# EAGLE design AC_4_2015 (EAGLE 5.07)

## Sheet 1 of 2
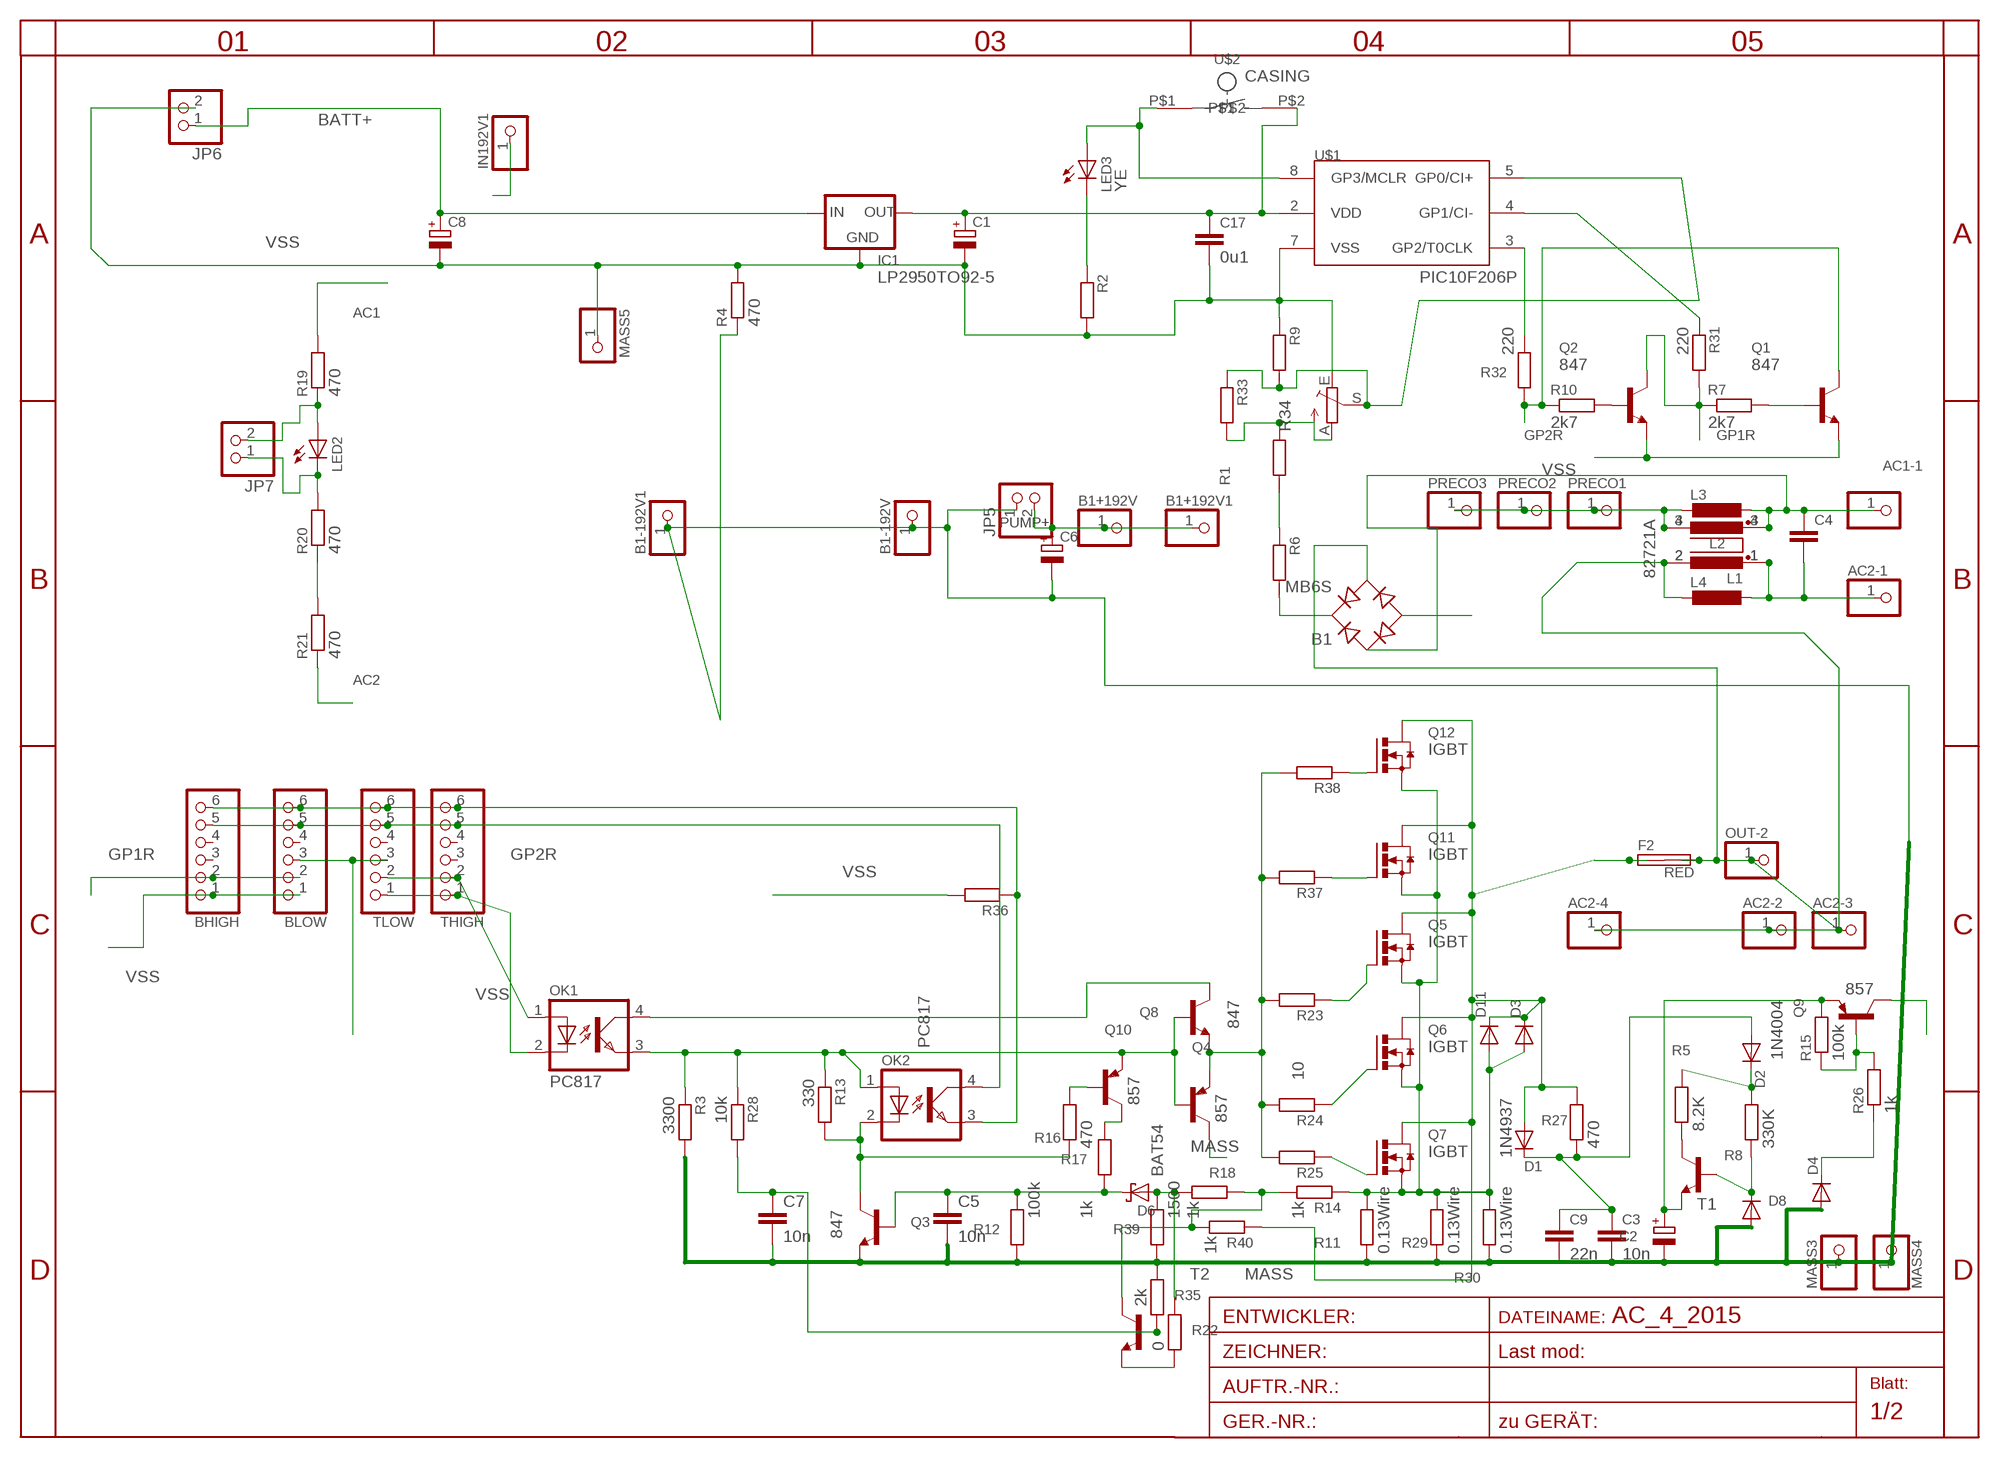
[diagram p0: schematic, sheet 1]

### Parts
AC1-1  PINHD-1X14.5MM  [1X4MM5]
AC2-1  PINHD-1X14.5MM  [1X4MM5]
AC2-2  PINHD-1X13MM2  [1X3MM2]
AC2-3  PINHD-1X13MM2  [1X3MM2]
AC2-4  PINHD-1X12MM3  [1X2MM3]
B1  MB6S  [SOIC-4]
B1+192V  PINHD-1X13MM2  [1X3MM2]
B1+192V1  PINHD-1X13MM2  [1X3MM2]
B1-192V  PINHD-1X13MM2  [1X3MM2]
B1-192V1  PINHD-1X13MM2  [1X3MM2]
BHIGH  PINHD-1X6  [1X06BOX]
BLOW  PINHD-1X6  [1X06BOX]
C1  CPOL-EUE5-6  [E5-6]
C2  CPOL-EUE2.5-5  [E2,5-5]
C3  10n  C-EU025_050-050X075  [C025_050-050X075]
C4  C-EU102_152-062X184  [C102_152-062X184]
C5  10n  C-EUC0805  [C0805]
C6  CPOL-EUE10-20  [EB20D]
C7  10n  C-EUC0805  [C0805]
C8  CPOL-EUE5-5  [E5-5]
C9  22n  C-EU102-043X133  [C102-043X133]
C17  0u1  C-EUC1206  [C1206]
D1  1N4937  1N4004DO41-10  [DO41-10]
D2  1N4004  [DO41-20]
D3  DIODE-SMC  [SMC]
D4  DIODE-MINIMELF  [MINIMELF]
D6  BAT54  [SOT23]
D8  DIODE-MINIMELF  [MINIMELF]
D11  DIODE-SMC  [SMC]
F2  SHK20L7MM5  [7MM5]
IC1  LP2950TO92-5  [T092-5]
IN192V1  PINHD-1X13MM2  [1X3MM2]
JP5  PINHD-1X2STR  [1X02]
JP6  PINHD-1X2STR  [1X02]
JP7  PINHD-1X2STR  [1X02]
L1  R1405VB1  [B1]
L2  82721A  [82721A]
L3  L-EU2200-15.24  [2200-15.24]
L4  L-EU2200-15.24  [2200-15.24]
LED2  LED3MM  [LED3MM]
LED3  YE  LEDCHIPLED_1206  [CHIPLED_1206]
MASS3  PINHD-1X13MM2  [1X3MM2]
MASS4  PINHD-1X13MM2  [1X3MM2]
MASS5  PINHD-1X11MM6  [1X1MM8]
OK1  PC817  [DIL04]
OK2  PC817  [DIL04]
OUT-2  PINHD-1X13MM2  [1X3MM2]
PRECO1  PINHD-1X12MM3  [1X2MM3]
PRECO2  PINHD-1X13MM2  [1X3MM2]
PRECO3  PINHD-1X13MM2  [1X3MM2]
Q1  847  BC847ALT1SMD  [SOT23]
Q2  847  BC847ALT1SMD  [SOT23]
Q3  847  BC846ALT1SMD  [SOT23]
Q4  857  BC857ALT1SMD  [SOT23-BEC]
Q5  IGBT  N-HEXFET_DPAK-  [TO252]
Q6  IGBT  N-HEXFET_DPAK-  [TO252]
Q7  IGBT  N-HEXFET_DPAK-  [TO252]
Q8  847  BC846ALT1SMD  [SOT23]
Q9  857  BC857ALT1SMD  [SOT23-BEC]
Q10  857  BC857ALT1SMD  [SOT23-BEC]
Q11  IGBT  N-HEXFET_DPAK-  [TO252]
Q12  IGBT  N-HEXFET_DPAK-  [TO252]
R1  R-EU_0207/30  [0207/30]
R2  R-EU_R0805  [R0805]
R3  3300  R-EU_R0805  [R0805]
R4  470  R-EU_0204/5  [0204/5]
R5  8.2K  R-EU_0204/5  [0204/5]
R6  R-EU_0207/60  [0207/60]
R7  2k7  R-EU_R0805  [R0805]
R8  330K  R-EU_0204/5  [0204/5]
R9  R-EU_R0805  [R0805]
R10  2k7  R-EU_R0805  [R0805]
R11  0.13Wire  R-EU_0204/5  [0204/5]
R12  100k  R-EU_R0805  [R0805]
R13  330  R-EU_R1206  [R1206]
R14  1k  R-EU_R0805  [R0805]
R15  100k  R-EU_R0805  [R0805]
R16  470  R-EU_R0805  [R0805]
R17  1k  R-EU_R1206  [R1206]
R18  1k  R-EU_R0805  [R0805]
R19  470  R-EU_0204/5  [0204/5]
R20  470  R-EU_0204/2V  [0204V]
R21  470  R-EU_0204/5  [0204/5]
R22  0  R-EU_R0805  [R0805]
R23  R-EU_0207/12  [0207/12]
R24  R-EU_0207/15  [0207/15]
R25  10  R-EU_0207/12  [0207/12]
R26  1k  R-EU_R0805  [R0805]
R27  470  R-EU_0207/10  [0207/10]
R28  10k  R-EU_R0805  [R0805]
R29  0.13Wire  R-EU_0204/5  [0204/5]
R30  0.13Wire  R-EU_0204/5  [0204/5]
R31  220  R-EU_R1206  [R1206]
R32  220  R-EU_R1206  [R1206]
R33  R-EU_R0805  [R0805]
R34  TRIM_EU-S64W  [S64W]
R35  2k  R-EU_R0805  [R0805]
R36  R-EU_0207/12  [0207/12]
R37  R-EU_0207/15  [0207/15]
R38  R-EU_0207/10  [0207/10]
R39  1500  R-EU_R0805  [R0805]
R40  1k  R-EU_R1206  [R1206]
T1  -NPN-TO92-EBC  [TO92-EBC]
T2  -NPN-TO92-EBC  [TO92-EBC]
THIGH  PINHD-1X6  [1X06BOX]
TLOW  PINHD-1X6  [1X06BOX]
U$1  PIC10F206P  [DIL8]
U$2  CASING  [CASING]

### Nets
AC1: AC1-1.1 B1.~1(AC1) C4.1 L1.3 L2.4 L3.1 R19.2
AC2: R21.1
ACN: AC2-1.1 C4.2 L1.1 L2.1 L4.1
BATT+: BLOW.3 C8.+ IC1.3(IN) JP6.1 TLOW.3
BLACK: L1.4 L2.3 L3.2 PRECO1.1 PRECO2.1 PRECO3.1 ; also sheet 2
D1: D1.A D3.C D11.C F2.1A F2.1B Q5.3(D) Q6.3(D) Q7.3(D) Q11.3(D) Q12.3(D) R27.2 R40.2
GP1R: BHIGH.2 BLOW.2 Q2.3(C) R7.1 R31.2
GP2R: OK1.1(A) Q1.3(C) R10.1 R32.2 THIGH.2 TLOW.2
GP3: BHIGH.6 BLOW.6 LED3.A OK2.3(EMIT) R36.1 THIGH.6 TLOW.6 U$1.8(GP3/MCLR) U$2.P$1
MASS: B1-192V1.1 B1-192V.1 B1.- C2.- C3.3 C5.2 C6.- C7.2 C9.2 D4.A D8.A JP5.1 MASS3.1 MASS4.1 Q3.2(E) Q4.C R3.2 R4.1 R11.1 R12.2 R29.1 R30.1 R35.2 R39.2 ; also sheet 2
N$1: R9.2 R33.1 R34.S U$1.5(GP0/CI+)
N$2: C3.1 C9.1 D1.C D2.A R27.1
N$3: R1.2 R6.1
N$4: Q2.1(B) R10.2
N$6: JP7.2 LED2.A R19.1
N$7: Q1.1(B) R7.2
N$9: JP7.1 LED2.K(C) R20.2
N$11: C5.1 D6.3(C) Q3.1(B) R12.1 R17.2
N$12: OK2.2(C) Q3.3(C) R13.2 R16.1
N$13: R20.1 R21.2
N$14: R14.1 R18.2 R40.1 T2.C
N$15: LED3.C R2.1
N$16: Q10.B R16.2
N$17: Q10.C R17.1
N$20: D2.C R5.2 R8.2
N$25: Q12.1(G) R38.1
N$26: Q6.1(G) R24.1
N$27: Q5.1(G) R23.1
N$33: B1.+ R6.2
N$34: R5.1 T1.C
N$35: D4.C R26.1
N$36: D8.C R8.1 T1.B
N$37: Q4.E Q8.2(E) R23.2 R24.2 R25.2 R37.2 R38.2
N$38: C2.+ Q9.E R15.2 T1.E
N$39: R31.1 U$1.4(GP1/CI-)
N$40: C7.1 R28.2 R35.1 T2.B
N$41: Q9.B R15.1 R26.2
N$42: R1.1 R33.2 R34.A
N$43: R32.1 U$1.3(GP2/T0CLK)
N$45: R22.1 T2.E
N$46: Q11.1(G) R37.1
N$47: Q7.1(G) R25.1
N$48: D6.1(A) R18.1 R22.2 R39.1
PP1: OK1.3(EMIT) OK2.1(A) Q4.B Q8.1(B) Q10.E R3.1 R13.1 R28.1
PUMP+: B1+192V1.1 B1+192V.1 C6.+ IN192V1.1 JP5.2 ; also sheet 2
RED: AC2-2.1 AC2-3.1 AC2-4.1 B1.~2(AC2) F2.2A F2.2B L1.2 L2.2 L4.2 OUT-2.1 ; also sheet 2
SRC1: D3.A D11.A Q5.2(S) Q6.2(S) Q7.2(S) Q11.2(S) Q12.2(S) R11.2 R14.2 R29.2 R30.2
V_OK: OK1.4(COL) Q8.3(C) Q9.C
VDD: BHIGH.5 BLOW.5 C1.+ C17.1 IC1.1(OUT) OK2.4(COL) THIGH.5 TLOW.5 U$1.2(VDD) U$2.P$2
VSS: BHIGH.1 BLOW.1 C1.- C8.- C17.2 IC1.2(GND) JP6.2 MASS5.1 OK1.2(C) Q1.2(E) Q2.2(E) R2.2 R4.2 R9.1 R34.E R36.2 THIGH.1 TLOW.1 U$1.7(VSS)
Unconnected: BHIGH.3 BHIGH.4 BLOW.4 THIGH.3 THIGH.4 TLOW.4

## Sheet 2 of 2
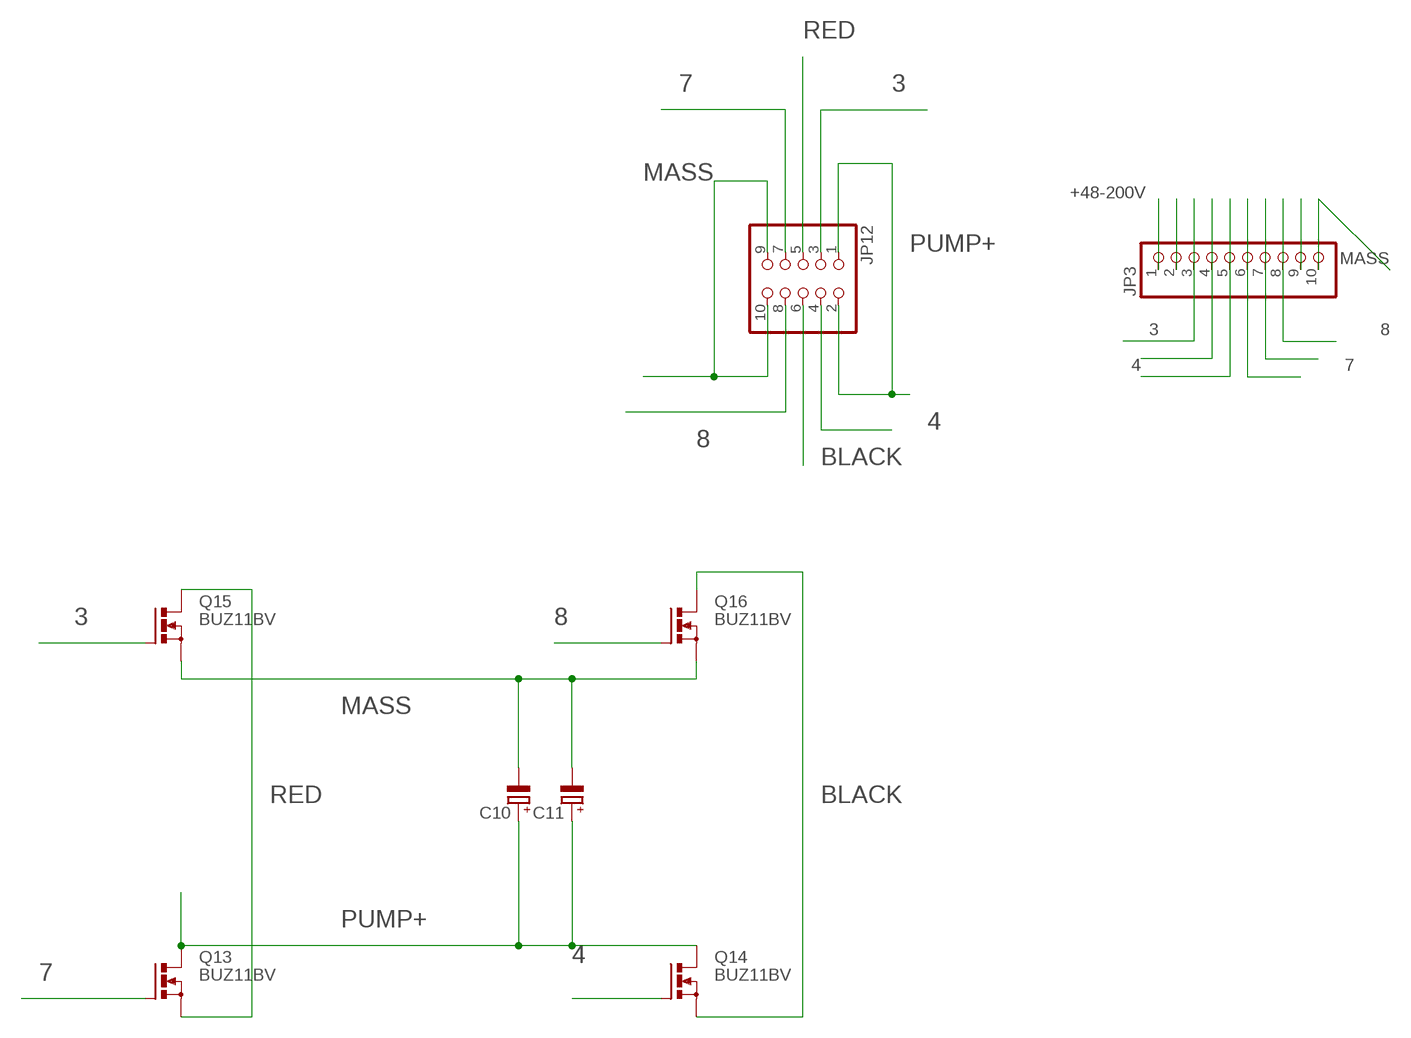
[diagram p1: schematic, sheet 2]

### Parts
C10  CPOL-EUE7.5-18  [E7,5-18]
C11  CPOL-EUE7.5-18  [E7,5-18]
JP3  PINHD-1X10  [1X10WIDE]
JP12  PINHD-2X5  [2X05]
Q13  BUZ11BV  [TO220BV]
Q14  BUZ11BV  [TO220BV]
Q15  BUZ11BV  [TO220BV]
Q16  BUZ11BV  [TO220BV]

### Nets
3: JP3.3 JP12.3 Q15.G
4: JP3.4 JP12.4 Q14.G
7: JP3.7 JP12.7 Q13.G
8: JP3.8 JP12.8 Q16.G
+48-200V: JP3.1
BLACK: JP3.6 JP12.6 Q14.S Q16.D ; also sheet 1
MASS: C10.- C11.- JP3.10 JP12.9 JP12.10 Q15.S Q16.S ; also sheet 1
N$44: JP3.2
N$49: JP3.9
PUMP+: C10.+ C11.+ JP12.1 JP12.2 Q13.D Q14.D ; also sheet 1
RED: JP3.5 JP12.5 Q13.S Q15.D ; also sheet 1

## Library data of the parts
AC1-1 AC2-1-AC2-4 B1+192V B1+192V1 B1-192V B1-192V1 IN192V1 MASS3-MASS5 OUT-2 PRECO1-PRECO3 = pinhead:PINHD-1X1: PIN HEADER
B1 = rectifier:MB*S: Bridge Rectifier Source: http://www.fairchildsemi.com/ds/MB/MB6S.pdf
BHIGH BLOW THIGH TLOW = pinhead:PINHD-1X6: PIN HEADER
C1 C2 C8 = rcl-2:CPOL-EU: POLARIZED CAPACITOR, European symbol
C3 C9 C17 = rcl-2:C-EU: CAPACITOR, European symbol
C4 C5 C7 = rcl:C-EU: CAPACITOR, European symbol
C6 C10 C11 = rcl:CPOL-EU: POLARIZED CAPACITOR, European symbol
D1 D2 = diode:1N4004: DIODE
D3 D4 D8 D11 = diode:DIODE-: DIODE
D6 = diode:BAT54: Schottky Diodes
F2 = fuse:SHK20L: FUSE HOLDER 5 x 20 mm, SH contact, SHH1 Schukat, E1073 Buerklin
IC1 = v-reg:LP2950?*: Source: http://cache.national.com/ds/LP/LP2950.pdf
JP3 = pinhead:PINHD-1X10: PIN HEADER
JP5-JP7 = pinhead:PINHD-1X2: PIN HEADER
JP12 = pinhead:PINHD-2X5: PIN HEADER
L1 = inductor-nkl:R1405V: Übertrager (verlustarm) bis typ. 400kHz Power transformer (low loss) up to typ. 400kHz
L2 = inductors:82721A: FILTER
L3 L4 = rcl:L-EU: INDUCTOR, European symbol
LED2 LED3 = led:LED: LED
OK1 OK2 = optocoupler:PC817: SHARP OPTO COUPLER
Q1 Q2 = transistor-npn:BC847*: NPN Transistor
Q3 Q8 = transistor-npn:BC846*: NPN Transistor
Q4 Q9 Q10 = transistor-pnp:BC857*: PNP Transistror
Q5-Q7 Q11 Q12 = transistor-power:N-HEXFET_?-*: HEXFET® Power MOSFET
Q13-Q16 = transistor-power:BUZ11: N-CHANNEL MOS FET
R1-R33 R35-R40 = rcl-2:R-EU_: RESISTOR, European symbol
R34 = pot:TRIM_EU-: POTENTIOMETER
T1 T2 = transistor-neu-to92:*-NPN-: NPN Transistror
U$1 = microchip-5:PIC10F2*: uPC nW 0,25/0,5k Program Flash memory Comparator
U$2 = button:CASING

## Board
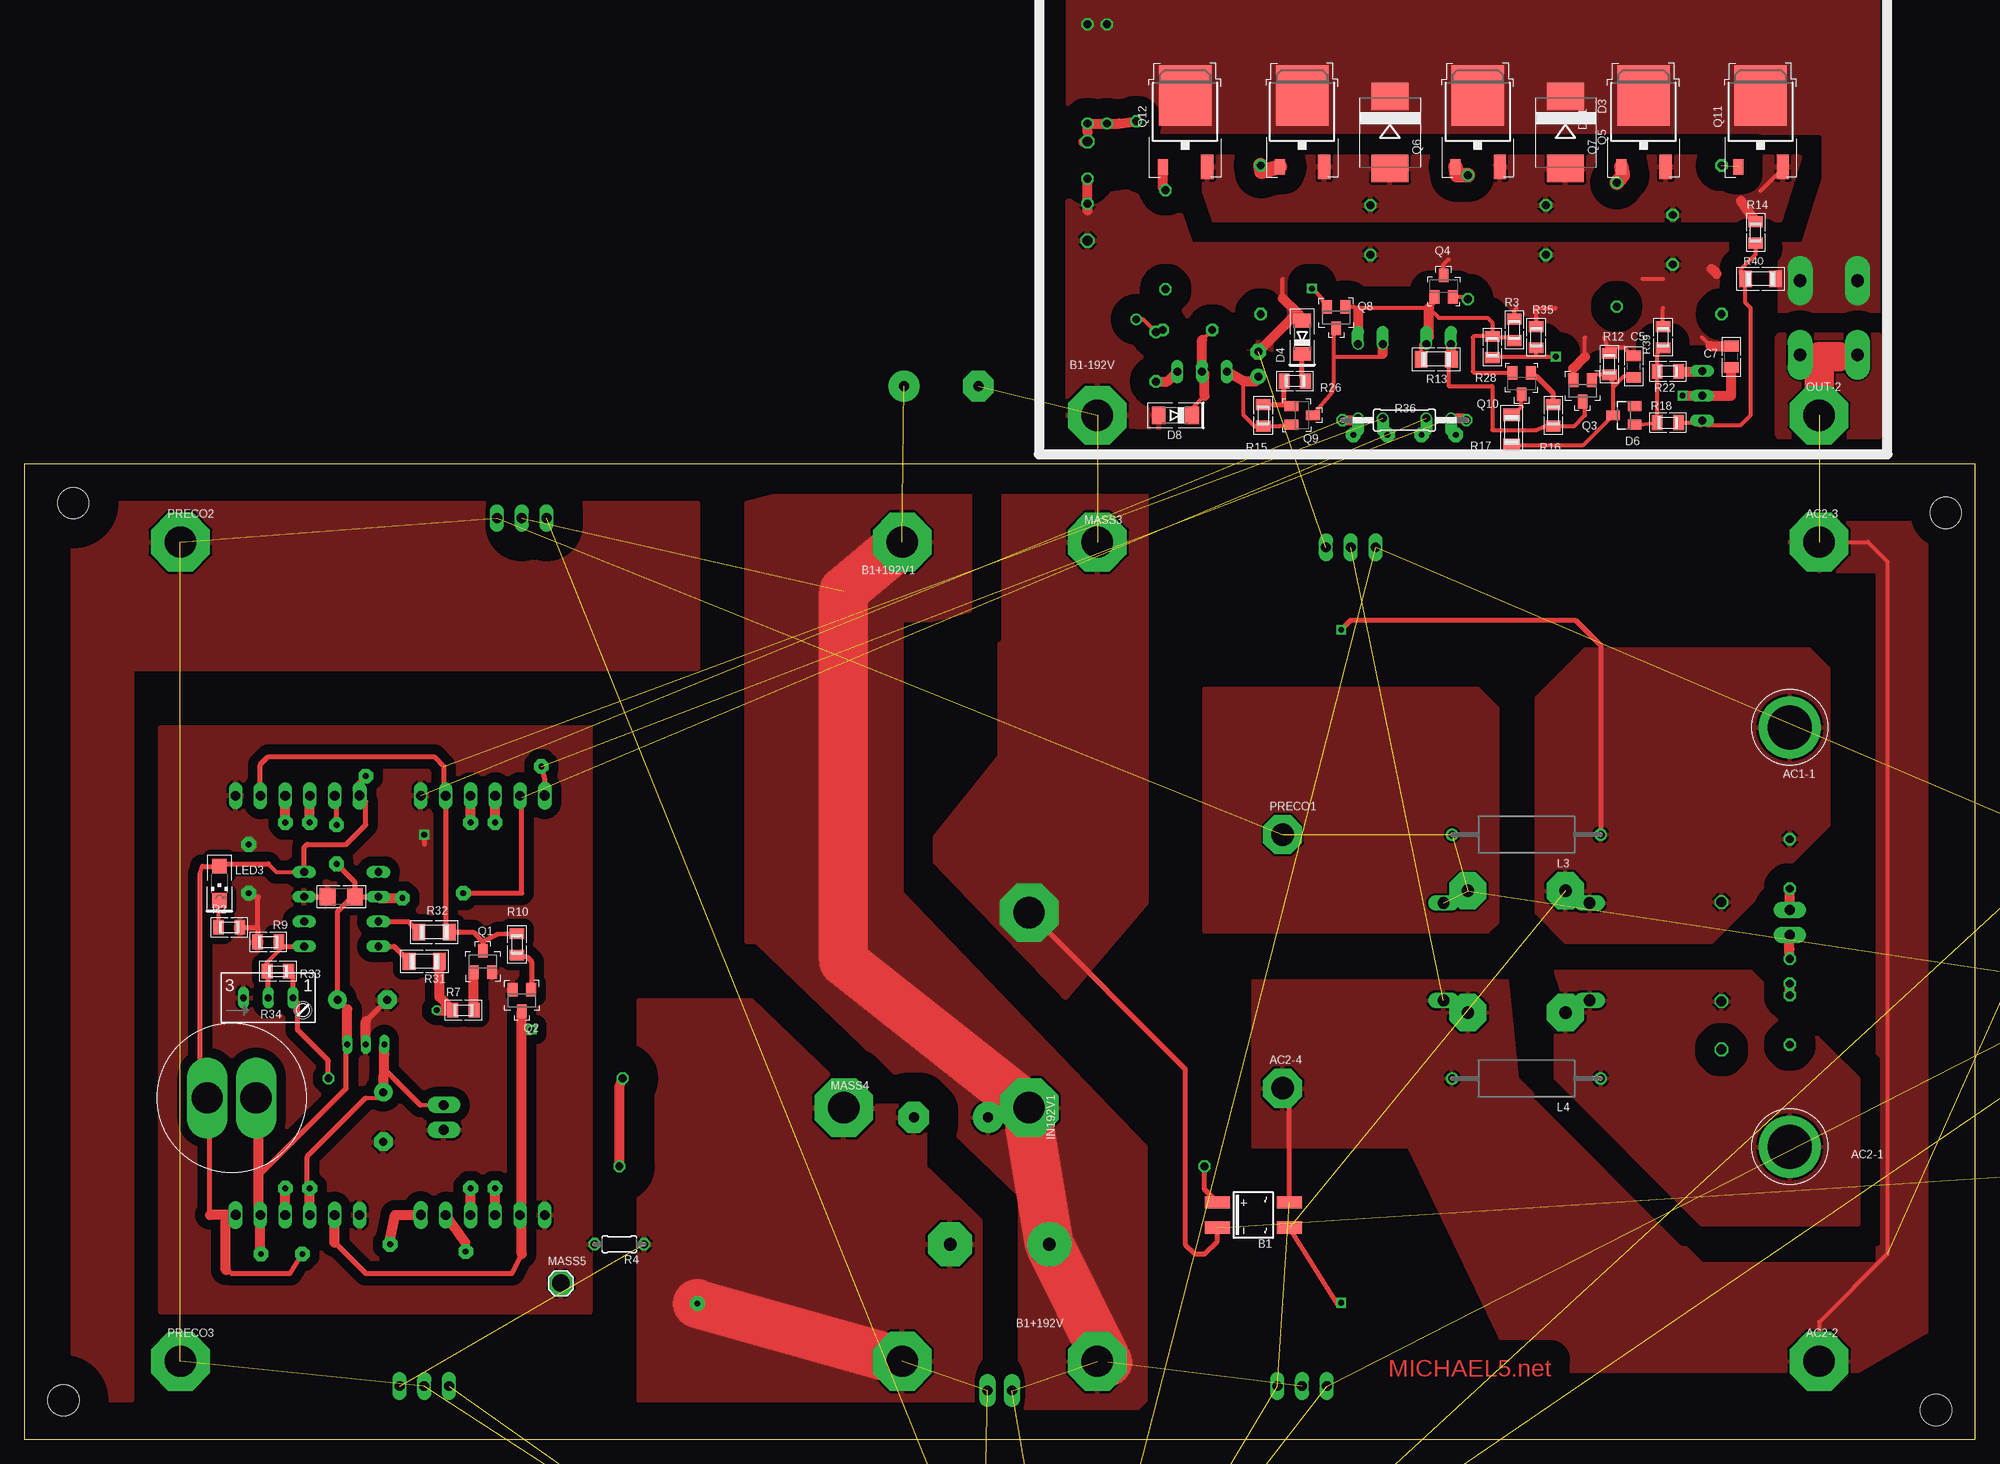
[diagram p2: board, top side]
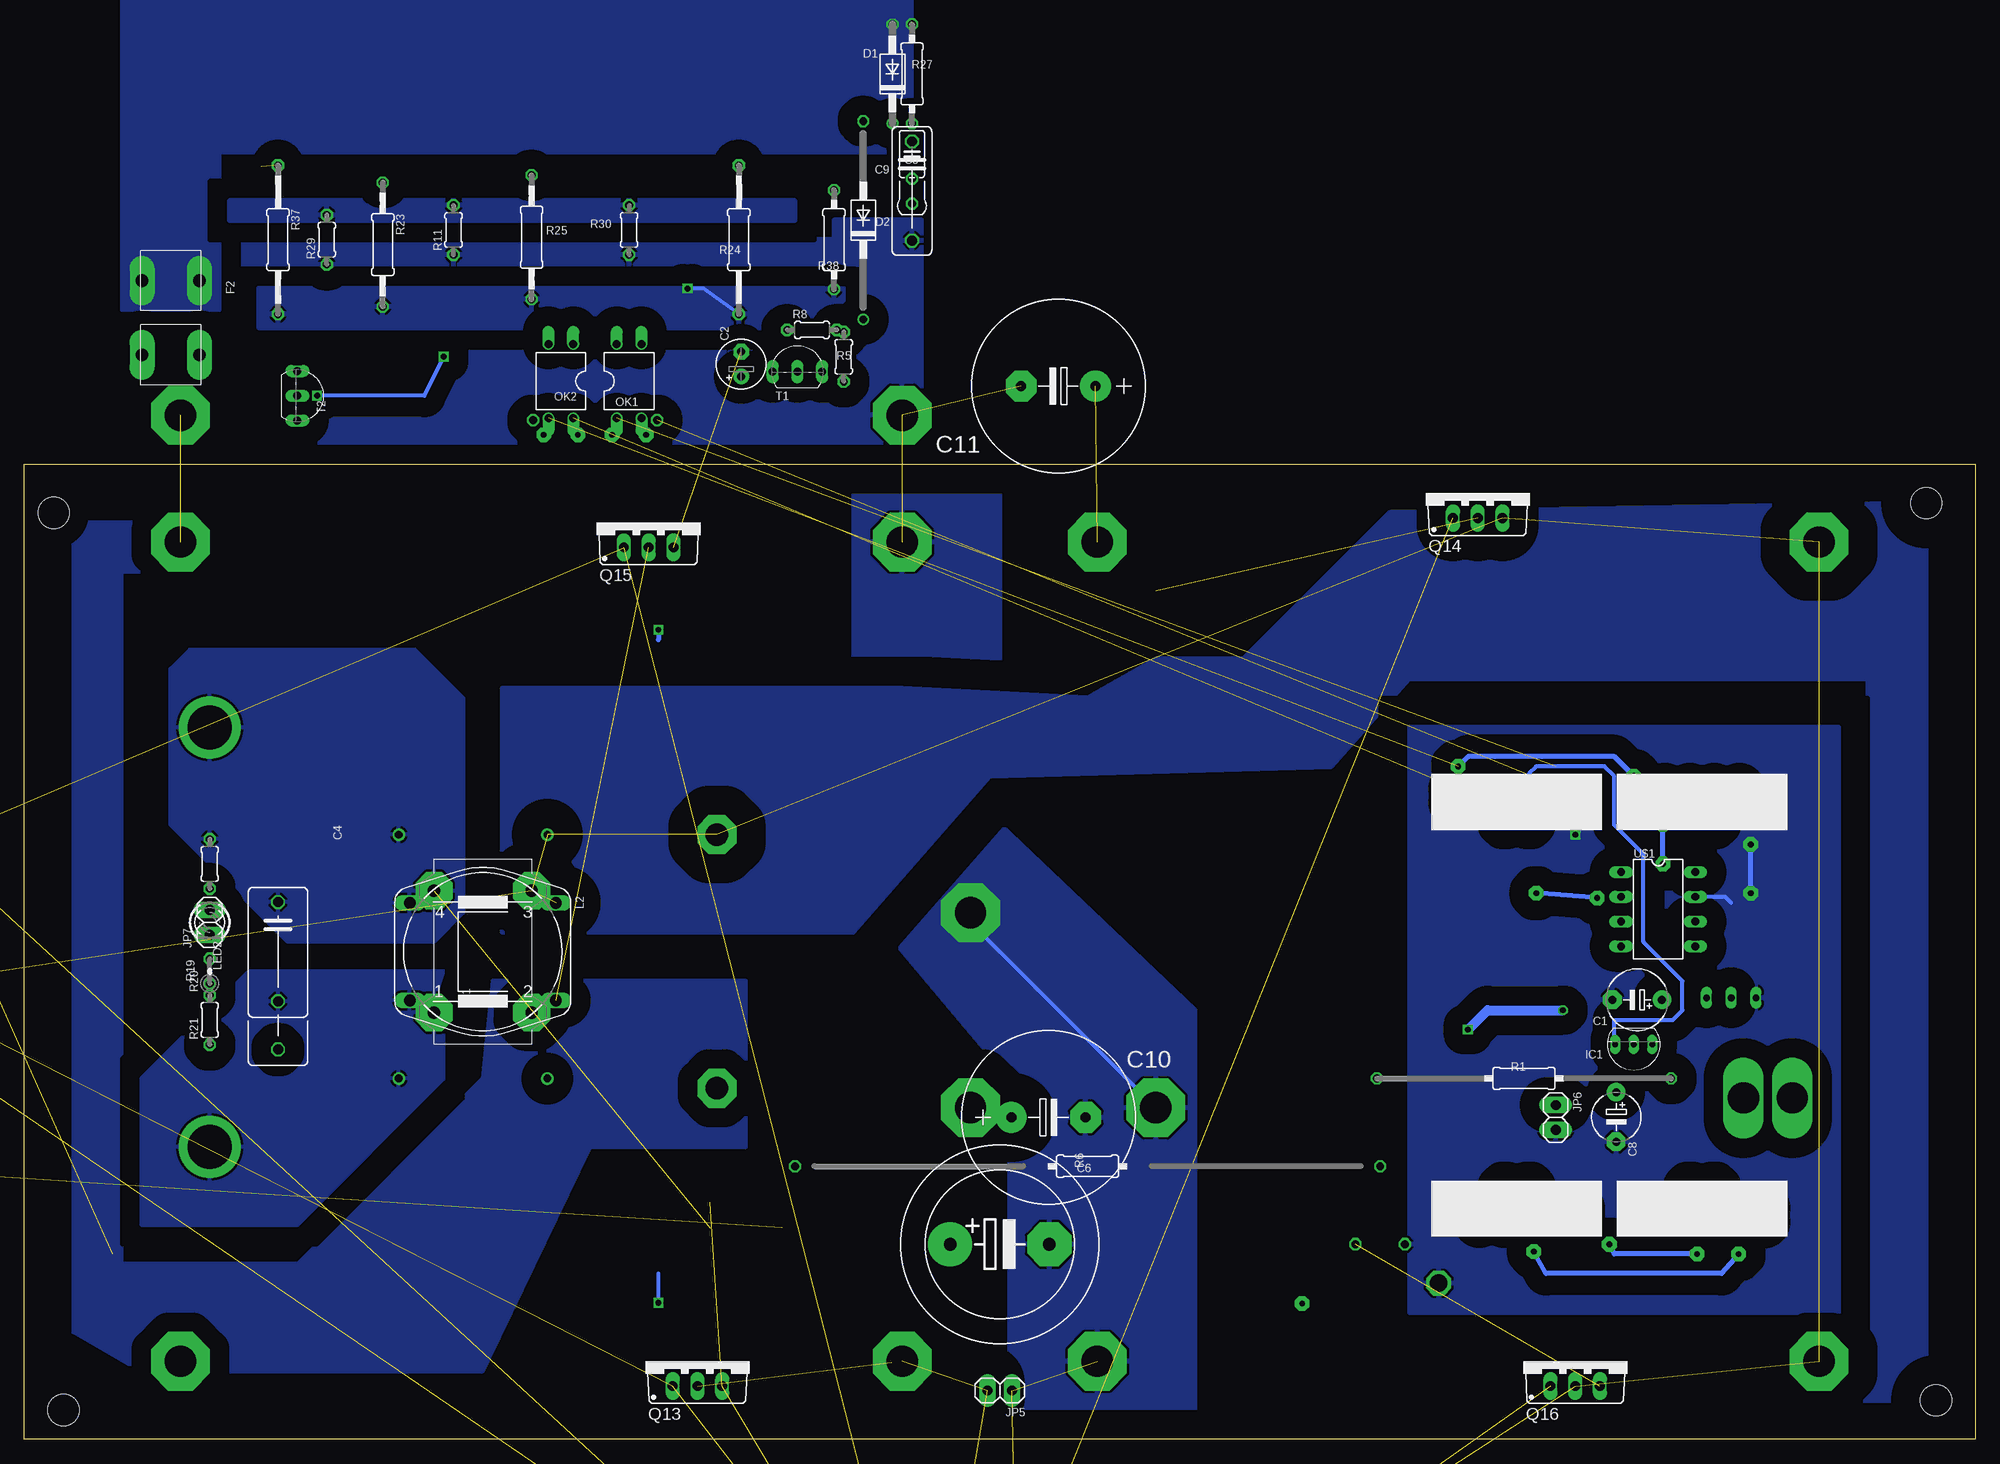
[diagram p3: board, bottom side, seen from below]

Size 200 x 100 mm. Coordinates in mm from the lower left corner, seen from the top.
Outline: 0,0 200,0 200,100 0,100 0,0
Copper layers (1*16): Top 0.035mm / dielectric 1.5mm / Bottom 0.035mm
Design rules "default *": minimum track width 12mil, minimum drill 24mil, track to track 8mil, track to pad 8mil, pad to pad 8mil, via to via 8mil, smd to smd 8mil, copper to edge 40mil, drill to drill 8mil, minimum pad ring 8mil, minimum via ring 8mil, stop-mask expansion 4mil, vias tented up to drill 0mil, thermal gap 10mil
Holes 3.2 mm at 5,96 4,4 197,95 196,3

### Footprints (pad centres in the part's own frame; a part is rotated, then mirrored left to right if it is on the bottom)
1X4MM5 = drill 4.5 pad 6.35 round: 1 0,0
1X3MM2 = drill 3.2 pad 6 octagon: 1 0,0
1X2MM3 = drill 2.3 pad 4 octagon: 1 0,0
SOIC-4 = smd 1.27 x 2.54: + 1.3,3.685; - -1.3,3.685; ~1 -1.3,-3.685; ~2 1.3,-3.685
1X06BOX = drill 1 long: 1 -6.35,0; 2 -3.81,0; 3 -1.27,0; 4 1.27,0; 5 3.81,0 | drill 1.016 long: 6 6.35,0
E5-6 = drill 0.813 pad 1.905 round: + -2.54,0 | drill 0.813 pad 1.905 octagon: - 2.54,0
E2,5-5 = drill 0.813 pad 1.6 round: + -1.27,0 | drill 0.813 pad 1.6 octagon: - 1.27,0
C025_050-050X075 = drill 0.813 octagon: 1 -3.81,0; 2 0,0; 3 2.54,0
C102_152-062X184 = drill 1.016 octagon: 1 -5.08,0; 2 5.08,0; 3 10.033,0
C0805 = smd 1.1 x 1.5: 1 -1.1,0; 2 1.1,0
EB20D = drill 1.3 pad 4.5 round: + -5.08,0 | drill 1.3 pad 4.5 octagon: - 5.08,0
E5-5 = drill 0.813 pad 1.905 round: + -2.54,0 | drill 0.813 pad 1.905 octagon: - 2.54,0
C102-043X133 = drill 1.016 octagon: 1 -5.08,0; 2 5.08,0
E7,5-18 = drill 1.016 pad 3.15 round: + -3.81,0 | drill 1.016 pad 3.15 octagon: - 3.81,0
C1206 = smd 1.6 x 1.8: 1 -1.4,0; 2 1.4,0
DO41-10 = drill 0.8 octagon: A 5.08,0 | drill 0.8 round: C -5.08,0
DO41-20 = drill 0.8 octagon: A 10.16,0 | drill 0.8 round: C -10.16,0
SMC = smd 2.8 x 3.8: A 3.7,0; C -3.7,0
MINIMELF = smd 1.4 x 1.8: A 1.7,0; C -1.7,0
SOT23 = smd 1 x 1.4: 1 -0.95,-1.1; 2 0.95,-1.1; 3 0,1.1
7MM5 = drill 1.3 pad 2.54 long: 1A -3.8,2.94; 1B -3.8,-2.94; 2A 3.8,2.94; 2B 3.8,-2.94
T092-5 = drill 0.6 pad 0.813 long: 1 -1.905,0; 2 0,0; 3 1.905,0
1X10WIDE = drill 1.016 long: 1 -22.86,0; 2 -17.78,0; 3 -12.7,0; 4 -7.62,0; 5 -2.54,0; 6 2.54,0; 7 7.62,0; 8 12.7,0; 9 17.78,0; 10 22.86,0
1X02 = drill 1.016 pad 1.676 long: 1 -1.27,0; 2 1.27,0
2X05 = drill 1.016 octagon: 1 -5.08,-1.27; 2 -5.08,1.27; 3 -2.54,-1.27; 4 -2.54,1.27; 5 0,-1.27; 6 0,1.27; 7 2.54,-1.27; 8 2.54,1.27; 9 5.08,-1.27; 10 5.08,1.27
B1 = drill 1.27 pad 3.81 octagon: 1 -6.25,5; 2 -6.25,-5; 3 6.25,5; 4 6.25,-5
82721A = drill 1.194 long: 1 7.493,5.004; 2 -7.493,5.004; 3 -7.493,-5.004; 4 7.493,-5.004
2200-15.24 = drill 0.8 pad 1.27 round: 1 -7.62,0; 2 7.62,0
LED3MM = drill 0.8 pad 1.27 octagon: A -1.27,0; K 1.27,0
CHIPLED_1206 = smd 1.5 x 1.5: A 0,-1.75; C 0,1.75
1X1MM8 = drill 1.8 pad 2.54 octagon: 1 0,0
DIL04 = drill 0.813 offset: 1 -1.27,-3.81; 2 1.27,-3.81; 3 1.27,3.81; 4 -1.27,3.81
SOT23-BEC = smd 1 x 1.4: B -0.95,-1.1; C 0,1.1; E 0.95,-1.1
TO252 = smd 1 x 1.6: 1 -2.28,-3.53 | smd 1.27 x 2.54: 2 2.28,-3.53 | smd 5.4 x 6.2: 3 0,3.77
TO220BV = drill 1.016 long: D 0,-2.54; G -2.54,-2.54; S 2.54,-2.54
0207/30 = drill 0.813 octagon: 1 -15.08,0; 2 15.08,0
R0805 = smd 1.1 x 1.5: 1 -1.1,0; 2 1.1,0
0204/5 = drill 0.8 pad 1.27 octagon: 1 -2.54,0; 2 2.54,0
0207/60 = drill 0.813 octagon: 1 -30,0; 2 30,0
R1206 = smd 1.3 x 1.7: 1 -1.55,0; 2 1.55,0
0204V = drill 0.8 pad 1.27 octagon: 1 -1.27,0; 2 1.27,0
0207/12 = drill 0.813 octagon: 1 -6.35,0; 2 6.35,0
0207/15 = drill 0.8 pad 1.27 octagon: 1 -7.62,0; 2 7.62,0
0207/10 = drill 0.813 octagon: 1 -5.08,0; 2 5.08,0
S64W = drill 0.7 long: A 2.54,1.27; E -2.54,1.27; S 0,1.27
TO92-EBC = drill 0.813 long: B 0,-1.27; C 2.54,-1.27; E -2.54,-1.27
DIL8 = drill 0.8 long: 1 -3.81,-3.81; 2 -1.27,-3.81; 3 1.27,-3.81; 4 3.81,-3.81; 5 3.81,3.81; 6 1.27,3.81; 7 -1.27,3.81; 8 -3.81,3.81
CASING = drill 3.2 pad 3.81 long: P$1 -2.5,0; P$2 2.5,0

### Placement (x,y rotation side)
AC1-1  181,73 180 top
AC2-1  181,30 180 top
AC2-2  184,8 0 top
AC2-3  184,92 0 top
AC2-4  129,36 0 top
B1  126,23 90 top
B1+192V  110,8 0 top
B1+192V1  90,92 180 top
B1-192V  not placed on the board
B1-192V1  90,8 0 top
BHIGH  47,23 0 bottom
BLOW  28,23 0 bottom
C1  34.65,45.07 180 bottom
C2  126.5,110.25 90 bottom  (outside the outline)
C3  109,129.25 270 bottom  (outside the outline)
C4  174,50 270 bottom
C5  165,110 90 top  (outside the outline)
C6  100,20 0 bottom
C7  175,111 90 top  (outside the outline)
C8  36.8,33.05 270 bottom
C9  109,128 270 bottom  (outside the outline)
C10  95,33 0 bottom
C11  not placed on the board
C17  32.49,55.63 180 top
D1  111,140 90 bottom  (outside the outline)
D2  114,125 90 bottom  (outside the outline)
D3  not placed on the board
D4  131,113 90 top  (outside the outline)
D6  164,105 90 top  (outside the outline)
D8  118,105 180 top  (outside the outline)
D11  not placed on the board
F2  185,115 270 bottom  (outside the outline)
IC1  35,40.5 180 bottom
IN192V1  103,34 270 top
JP3  not placed on the board
JP5  100,5 180 bottom
JP6  43,33 270 bottom
JP7  181,53 90 bottom
JP12  not placed on the board
L1  153,50 90 bottom
L2  153,50 180 bottom
L3  154,62 180 top
L4  154,37 180 top
LED2  181,53 270 bottom
LED3  20,57 180 top
MASS3  110,92 0 top
MASS4  84,34 0 top
MASS5  55,16 0 top
OK1  138,108.5 0 bottom  (outside the outline)
OK2  145,108.5 180 bottom  (outside the outline)
OUT-2  184,105 0 top  (outside the outline)
PRECO1  129,62 0 top
PRECO2  16,92 0 top
PRECO3  16,8 0 top
Q1  47,49 0 top
Q2  51,45 180 top
Q3  159.75,107.5 180 top  (outside the outline)
Q4  145.5,118.25 0 top  (outside the outline)
Q5  166,134 0 top  (outside the outline)
Q6  131,134 0 top  (outside the outline)
Q7  149,134 0 top  (outside the outline)
Q8  134.5,115 180 top  (outside the outline)
Q9  131,105 270 top  (outside the outline)
Q10  153.5,108.25 180 top  (outside the outline)
Q11  178,134 0 top  (outside the outline)
Q12  119,134 0 top  (outside the outline)
Q13  131,8 0 bottom
Q14  51,97 0 bottom
Q15  136,94 0 bottom
Q16  41,8 0 bottom
R1  46.25,37 180 bottom
R2  21,52.5 0 top
R3  152.75,113.75 90 top  (outside the outline)
R4  61,20 180 top
R5  116,111 90 bottom  (outside the outline)
R6  91,28 180 bottom
R7  45,44 0 top
R8  119.25,113.75 0 bottom  (outside the outline)
R9  25,51 0 top
R10  50.5,50.75 270 top
R11  not placed on the board
R12  162.5,110.25 90 top  (outside the outline)
R13  144.75,110.75 0 top  (outside the outline)
R14  177.5,123.75 90 top  (outside the outline)
R15  127,105 270 top  (outside the outline)
R16  156.75,105 90 top  (outside the outline)
R17  152.5,103.5 270 top
R18  168.5,104.25 0 top  (outside the outline)
R19  181,59 90 bottom
R20  181,48 90 bottom
R21  181,43 90 bottom
R22  168.5,109.5 180 top  (outside the outline)
R23  163.25,122.5 270 bottom  (outside the outline)
R24  126.75,123 270 bottom  (outside the outline)
R25  148,123.25 270 bottom  (outside the outline)
R26  130.25,108.5 180 top  (outside the outline)
R27  109,140 90 bottom  (outside the outline)
R28  150.5,112 270 top  (outside the outline)
R29  not placed on the board
R30  not placed on the board
R31  41,49 0 top
R32  42,52 0 top
R33  26,48 0 top
R34  25,44 0 top
R35  155,113 90 top  (outside the outline)
R36  141.5,104.5 180 top  (outside the outline)
R37  not placed on the board
R38  117,123 270 bottom  (outside the outline)
R39  168,113 90 top  (outside the outline)
R40  178,119 0 top  (outside the outline)
T1  120.75,110.75 0 bottom  (outside the outline)
T2  170.75,107 270 bottom  (outside the outline)
THIGH  28,66 180 bottom
TLOW  47,66 180 bottom
U$1  32.49,54.36 270 bottom
U$2  21.25,35 0 top

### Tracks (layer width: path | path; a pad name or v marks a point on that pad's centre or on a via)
3  (2 unrouted)
4  (2 unrouted)
7  (2 unrouted)
8  (2 unrouted)
AC1  (via drill 0.6)  (1 unrouted)
  Top 0.406: v135,14 134.7,13.7
  Top 0.5: 134.7,13.7 B1.~1 | L3.1 161.62,81.38 159,84 136,84 v135,83
  Bottom 0.406: v135,14 135,17
  Bottom 0.5: v135,83 135,82
  pour Bottom (isolate 2): 155,65 155,54 158,51 173,51 185,63 185,79 183,81 160,81 155,76
  pour Top (isolate 2): 155,65 155,54 158,51 173,51 185,63 185,79 183,81 160,81 155,76
ACN
  pour Bottom (isolate 2, rank 2): 157,48 177,48 188,37 188,22 172,22 157,37 157,44 158,45
  pour Top (isolate 2, rank 2): 157,48 177,48 188,37 188,22 172,22 157,37 157,44 158,45
BATT+
  Top 0.406: 40.6,34.27 JP6.1 | BLOW.3 29.27,25.73 29,26 | 35,35 36.21,35 C8.+
  Top 0.5: 36.86,38 40.6,34.27 | 29,26 29,29 35,35
  Top 1: IC1.3 36.91,39.48 36.86,38 C8.+
  Bottom 0.406: TLOW.3 45.73,68.27 45,69 38,69 37,68 37,63 34,60 34,51 30,47 30,44 31,43 37,43 37,40.59 IC1.3
BLACK  (9 unrouted)
  pour Top (isolate 3): 5,96 69,96 69,79 11,79 11,4 5,4
D1
  pour Top (isolate 2, rank 2, no thermals): 107,150 190,150 190,115 180,115 180,133 178,134 107,134
  pour Bottom (isolate 2, rank 2, no thermals): 109,148 190,148 190,115.82 180,115.82 180,132 109,132
GP1R  (via drill 0.6, 0.6 pad 1)
  Top 0.5: 31.81,20.19 35,17 50,17 51,19 | 51,22.81 BHIGH.2
  Top 1: 51,19 51,22.81 | 31.81,20.19 BLOW.2 | R31.2 42.55,45.35 R7.1 v42.25,44 | 51,42 51,23.19 BHIGH.2 | 51,42 Q2.3 | 51,42 v52,42
  Bottom 1: v42.25,44 50,44 v52,42
GP2R  (1 unrouted)
  Top 0.5: R10.1 48.55,51.8 47,51 | 47,51 Q1.3 | 47,51 46,52 R32.2 43.19,52.36 TLOW.2 43,66.19 43,69 42,70 25,70 24.19,69.19 THIGH.2
GP3  (via drill 0.6 pad 1.5)  (1 unrouted)
  Top 0.406: U$1.8 25.83,58.17 25,59 | LED3.A 20.25,59 | 18,58 18.25,58.75 | 18,36 19,35 U$2.P$1
  Top 0.5: 20.65,17.35 21.25,17 27.25,17 v28.5,19 | 19,23 19,31.5 U$2.P$1 | 20.65,22.65 21,23 | v37.5,20 37.5,20.5 | U$1.8 28.68,60.68 29,61 33,61 35,63 35,65.35 THIGH.6 34,66.35 34,67 v35,68 | TLOW.6 53.35,67.65 v53,69 | 20.25,59 25,59 | 18.25,58.75 LED3.A | 18,36 18,58
  Top 1: 19,23 BLOW.6 21,23 | 20.65,17.35 20.65,22.65 | 37.5,20.5 38,23 BHIGH.6 | OK2.3 147.66,104.69 R36.1
  Bottom 0.5: v28.5,19 37,19 v37.5,20 | v53,69 52,70 37,70 v35,68
INN
  pour Bottom (isolate 2, rank 3): 126,47 152,47 153,37 172,18 190,18 190,89 181,89 181,94 195,94 195,11 188,7 153,7 142,30 126,30
  pour Top: 180,113 190,113 190,112 190,103 180,103
MASS  (via drill 0.6 pad 1.5, 3.2 pad 6)  (8 unrouted)
  Top 0.406: 165.9,119 168,119 | 131,115 D4.A | 129,117 129,119 | C5.2 164.9,111.1 164,112 162.65,112 R12.2 162,113 | 157,116 155,116 R35.2 | 172,113 172.9,112.1 | Q4.C 145.5,120.5 146,121 | R3.2 152.75,115.75 153,116 | Q3.2 158.8,109.8 | 160,111 160,113 | R39.2 168,116
  Top 0.5: B1.- 122.31,20.32 121,19 120,19 119,20 119,38 v103,54
  Top 1: 173,120 173.5,119.5 | 130.5,115.5 131,115 | 130.5,115.5 129,117 | 172.9,112.1 C7.2 | 158.8,109.8 160,111 | C2.- 126.52,111.52 130.5,115.5 | 109,126 109,129
  Top 5: v69,13.92 B1-192V1.1
  Bottom 0.406: v103,54 103,53 MASS4.1
  pour Top (isolate 2, rank 3): 107,127 113,128 122,124 175,124 175,102 107,104
  pour Bottom (isolate 2, rank 3): 108,125 117,125 117,123 179,123 179,102 108,101
  pour Top (isolate 3, rank 3): 100,97 115,97 115,55 98,35 98,4 63,4 63,45 80,45 100,70
  pour Bottom (isolate 3, rank 4): 100,98 115,98 115,56 99,37 99,3 80,3 80,44 100,63
N$1
  Top 0.406: 25,47.9 R33.1 | 24.9,48.9 26.55,50.55
  Top 0.5: U$1.5 26.55,50.55 R9.2 | R34.S 25,47.9 | R33.1 24.9,48.9
N$2
  Top 0.5: 109,134 C9.1 C3.1
  Top 1: 109,134 R27.1 D1.C 112.24,134.92 D2.A | C9.1 108.54,133
N$3
  Top 1: R6.1 61,36.17 R1.2
N$4
  Top 0.5: R10.2 51.55,49.45 52,49 52,46.15 Q2.1
N$5  (via drill 0.6 pad 1.5)
  Top 1: 48.25,23 v48.25,25.75
N$6
  Top 1.016: JP7.2 R19.1
N$7
  Top 1: Q1.1 46.05,44.05 R7.2
N$8  (via drill 0.6 pad 1.5)
  other vias: 45.75,25.75
N$9
  Top 1.016: R20.2 180.96,50.27 JP7.1
N$10  (via drill 0.6 pad 1.5)
  other vias: 26.75,25.75
N$11
  Top 0.406: 162.9,107.9 D6.3 159.85,101.95 R17.2 | 162.9,107.9 164,109 164.9,109 C5.1 | 162.9,107.9 162.9,108.25 R12.1 161.15,109.15 Q3.1
N$12
  Top 0.406: R13.2 146,110.95 146,108 150.5,108 150.5,103.5 155,103.5 155.9,103.9 R16.1 158.9,103.9 160,105 160,106.15 Q3.3 | 146.3,112.78 OK2.2
  Top 1: R13.2 146.3,112.78
N$13
  Top 1.016: R21.2 R20.1
N$14
  Top 0.406: R14.1 177.5,121.5 176,120 176,119.45 R40.1 176.45,116.55 177,116 177,105 176,104 172.48,104 T2.C | R18.2 171.81,104.25
  Top 1: 171.81,104.25 T2.C
N$15
  Top 0.406: R2.1 19.9,55.15 LED3.C
N$16
  Top 0.5: R16.2 156.75,107.25 155,109 154.8,109 Q10.B
N$17
  Top 0.406: Q10.C 153.5,105.85 R17.1
N$18  (via drill 0.6 pad 1.5)
  Top 1: 29.25,23 v29.25,25.75
N$19  (via drill 0.6 pad 1.5)
  Top 1: v48.25,63.25 48.25,66
N$20
  Top 0.406: D2.C 114.7,114.84 R5.2 116.5,113.54 R8.2
N$21  (via drill 0.6 pad 1.5)
  other vias: 146.75,103
N$22  (via drill 0.6 pad 1.5)
  other vias: 143.25,103
N$23  (via drill 0.6 pad 1.5)
  other vias: 139.75,103
N$24  (via drill 0.6 pad 1.5)
  other vias: 136.25,103
N$25
  Top 1: Q12.1 116.72,128.36 R38.1
N$26
  Top 1.5: Q6.1 126.85,129.97 R24.1
N$27
  Top 1.5: R23.1 163.87,129.62 Q5.1
N$28  (via drill 0.6 pad 1.5)
  Top 1: v45.75,63.25 45.75,66
N$29  (via drill 0.6 pad 1.5)
  Top 1: v29.25,63.25 29.25,66
N$30  (via drill 0.6 pad 1.5)
  Top 1: v26.75,63.25 26.75,66
N$31
  Top 1: 45.75,23 45.75,25.5
N$32
  Top 1: 26.75,23 26.75,25.5
N$33
  Top 0.5: R6.2 121,25.61 B1.+
N$34
  Top 1: R5.1 117.19,108.46 T1.C
N$35
  Top 0.5: D4.C 131,108.85 R26.1
N$36
  Top 0.406: D8.C 119.7,105.7 121,107 | 121,109.23 T1.B | 120.75,112.71 R8.1
  Top 1: 121,107 121,109.23 | T1.B 120.75,112.71
N$37  (via drill 0.6)
  Top 0.406: Q8.2 132.8,117.2 v132,118 | Q4.E 147.75,117.15 R25.2
  Bottom 0.406: v132,118 130.37,118 R24.2 | R25.2 148,118
  pour Bottom (isolate 2, rank 2): 116,118 176,118 176,114 116,114
N$38
  Top 0.406: 126.25,108.48 C2.+ | 125,108.48 125,105 126.1,103.9 R15.2 128.75,103.9 Q9.E
  Top 1: 126.25,108.48 125,108.48 T1.E
N$39
  Top 0.5: U$1.4 37.9,50.55 R31.1
N$40  (via drill 0.6)
  Top 0.406: 155,111 150.4,111 R28.2 | 155,111 v157,111 | 155,111 R35.1
  Top 1: C7.1 175,107 T2.B v170,107
  Bottom 0.406: v170,107 159,107 v157,111
  Bottom 1: T2.B 172.35,107
N$41
  Top 0.406: 129.15,107.7 R26.2 | R15.1 128.1,106.1
  Top 0.5: 128.1,106.1 129,106.1 | 129,106.1 129.75,106.1 Q9.B | 129.15,107.7 129.15,106.25 129,106.1
N$42
  Top 0.406: 28,44.81 R34.A | 27.54,47.56 R33.2
  Top 0.5: 28,44.81 28,42 31,39 31.17,38.83 R1.1 | R34.A 27.54,47.56
N$43
  Top 0.5: U$1.3 39.36,53.09 R32.1
N$45
  Top 1: R22.1 171.98,109.5 T2.E
N$46  (1 unrouted)
N$47
  Top 1.5: R25.1 146.87,129.62 Q7.1
N$48
  Top 0.406: D6.1 165.15,104 R18.1 R22.2 167.4,111.3 R39.1
PP1
  Top 0.406: 144,116 137,116 136.73,115.73 136.36,116.1 Q8.1 | 144,113.08 OK2.1 143.2,112.28 R13.1 | Q4.B 144.55,116.55 144,116 | R28.1 148.6,113.1 148.5,113 148.5,109.5 148.65,109.35 Q10.E | R28.1 150.5,114.5 150,115 145,115 144,116 | R28.1 150.9,113.1 151,113 152.4,113 R3.1
  Top 1: 136.73,115.73 OK1.3 | 144,113.08 144,116
PRECOIL
  pour Bottom (isolate 3, rank 2): 5,96 60,95 75,80 84,80 91,76 110,77 151,77 151,52 115,52 101,68 66,69 58,78 11,78 11,10 20,10 20,4 5,4
  pour Top: 121,77 149,77 151,75 151,53 150,52 121,52
PUMP+  (6 unrouted)
  Top 5: B1+192V.1 111.08,7.92 C6.+ 103.08,31.92 IN192V1.1 84,49 84,87 B1+192V1.1
  pour Top (isolate 3): 74,96 74,51 75,51 102,25 102,2 113,2 115,4 115,30 90,56 90,84 93,84 97,85 97,97 78,97
RED  (5 unrouted)
  Top 0.406: AC2-3.1 189,92 191,90 191,19 184,12 184,9 | 129.69,35.31 AC2-4.1
  Top 0.5: B1.~2 129.69,35.31
  Top 1: F2.2A F2.2B 186.74,111 186,111
  Top 3: OUT-2.1 184,111 186,111
  pour Top (isolate 2, rank 3): 126,47 152,47 153,37 172,18 190,18 190,89 181,89 181,94 195,94 195,11 188,7 153,7 142,30 126,30
SRC1
  Top 0.406: Q11.2 180.28,130.28 178,128
  Top 1: R14.2 176.5,126.25 176,127
  pour Top (isolate 2): 121,131.5 182,131.5 180,125 122,125 121,128
  pour Bottom (isolate 2): 121,127 179,127 179,125 121,125
V_OK
  Top 0.406: Q9.C 134.1,107.35 134.25,108.5 134.25,111 | 134.25,111 134.25,113.65 Q8.3 | 139.27,111.27 139,111 134.25,111
  Top 1: 139.27,111.27 OK1.4
VDD  (via drill 0.6 pad 1.5)  (1 unrouted)
  Top 0.5: 33.09,44.09 C1.+ 32.11,54.11 34,56 34,55.52 C17.1 | C17.1 U$1.2 | 24,27 33,36 33,40 33.09,40.09 IC1.1 | v45.25,19.25 45.19,20.19 | 24,32.75 U$2.P$2 | v45,56 51,56 51,65.81 TLOW.5 | C17.1 33.89,57.11 v32,59 | v32,63 32,65.81 THIGH.5 | BLOW.5 24,23.19 | v24.25,19 24.19,19.31
  Top 1: IC1.1 33.09,44.09 | 24,32.75 24,27 24,23.19 | 45.19,20.19 BHIGH.5 | 24.19,19.31 BLOW.5 | v38.75,55.5 36.43,55.5 U$1.2
  Bottom 0.5: v45.25,19.25 44,17 26,17 v24.25,19 | v38.75,55.5 v45,56 | v32,59 v32,63
VSS  (via drill 0.6, 0.6 pad 1.5)  (1 unrouted)
  Top 0.5: 28.68,56 U$1.7 C17.2 | v23,56 23.37,55.63 24,55.63 23.9,55.53 23.9,52.5 | 23.9,52.5 R9.1 | 35,42.88 C1.- | R2.2 23.9,52.5 | v41,62 41,61
  Top 1: IC1.2 35,42.88 | R36.2 136.54,104.5 OK1.2
  Bottom 0.406: U$1.7 25.63,55.63 25,55
  Bottom 0.5: v23,56 v23,61 | TLOW.1 40.65,62.35 v41,62
  pour Bottom (isolate 2): 14,73 58,73 58,13 14,13
  pour Top (isolate 1): 14,73 58,73 58,13 14,13

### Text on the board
Top: MICHAEL5.net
